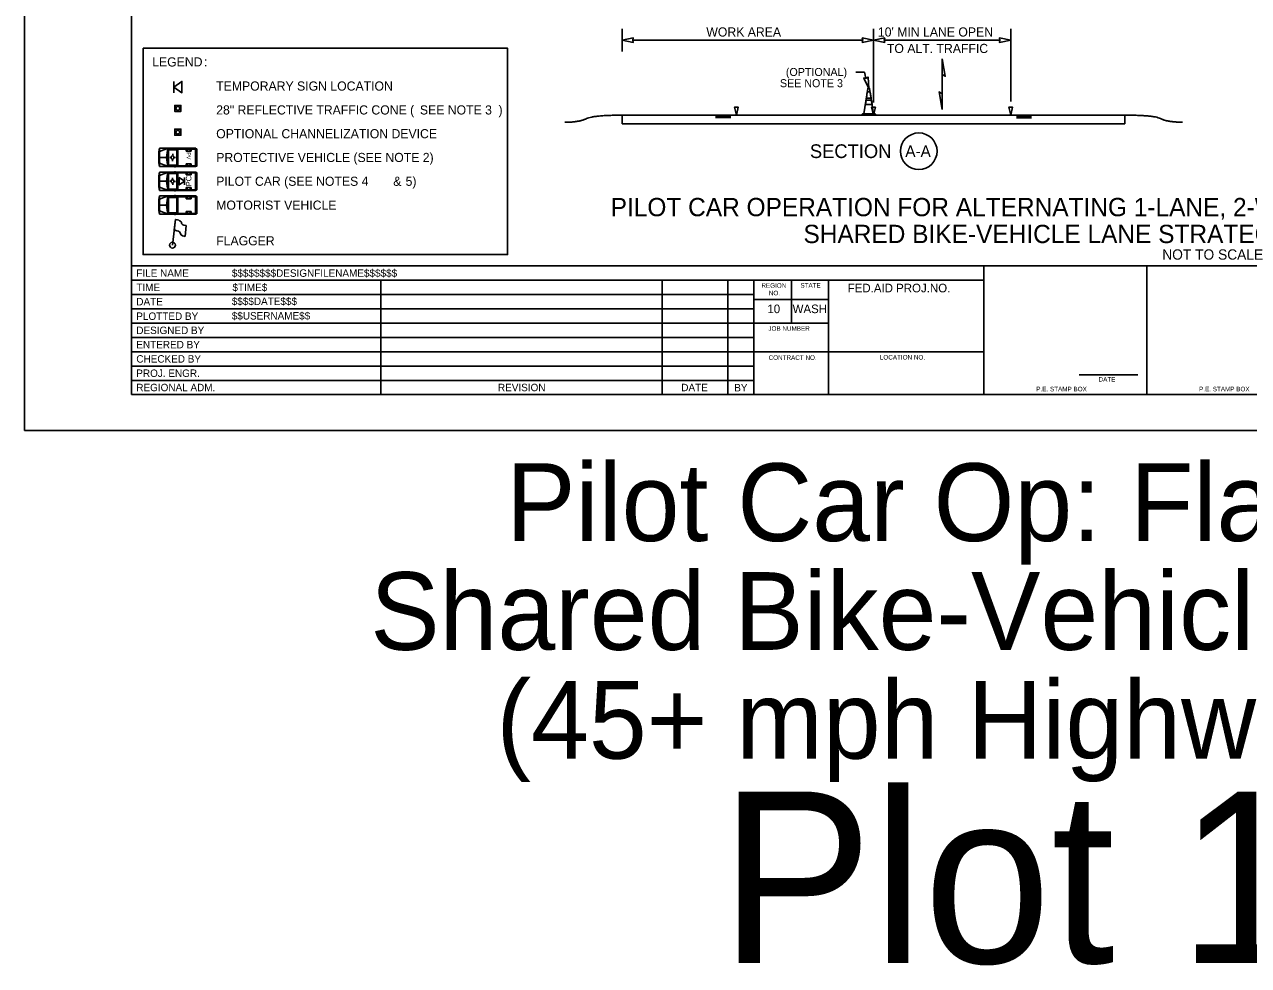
# Model space of a CAD drawing. Extents: x 99999.1 to 100095.7, y 99995 to 100010.7.
# Drawn here: x 99999.06 to 100009.77, y 99995.01 to 100003.24 of the extents above; entities that cross this region are included whole.
import ezdxf

# ---------------------------------------------------------------- set-up
doc = ezdxf.new("R2010")
doc.units = 0
for name, color, linetype in [('SH_DE_DetailHeading1Text', 7, 'Continuous'), ('SH_GI_PlotLimits', 7, 'Continuous'), ('SH_GI_SheetBorder', 7, 'Continuous'), ('SH_GI_SheetLocationText', 7, 'Continuous'), ('SH_GI_SheetTextInCells', 7, 'Continuous'), ('SH_GI_TitleBlockText', 7, 'Continuous'), ('TR_WZ_FlaggingStation', 7, 'Continuous'), ('TR_WZ_MotoristVehicle', 7, 'Continuous'), ('TR_WZ_PortableSignMountBlk-Org', 7, 'Continuous'), ('TR_WZ_PortableSignMountBlk-Wht', 7, 'Continuous'), ('TR_WZ_ProtectiveVehicle', 7, 'Continuous'), ('TR_WZ_TrafficCone', 7, 'Continuous'), ('TR_WZ_TrafficConeElev', 7, 'Continuous'), ('TR_WZ_WorkZoneDetails', 7, 'Continuous'), ('TR_WZ_WorkZoneTextCurrent', 7, 'Continuous')]:
    doc.layers.add(name, color=color, linetype=linetype)

msp = doc.modelspace()

# ---------------------------------------------------------------- linework, layer by layer
at = {"layer": 'SH_GI_PlotLimits'}
msp.add_lwpolyline([(99999.062, 99999.687), (100016.062, 99999.687), (100016.062, 100010.687), (99999.062, 100010.687)], close=True, dxfattribs=at)
at = {"layer": 'SH_GI_SheetBorder'}
for p, q in [((100000, 100010.375), (100000, 100000)), ((100000, 100001.126), (100015.75, 100001.126)), ((100007.457, 100000), (100007.457, 100001.126)), ((100008.883, 100000), (100008.883, 100001.126)), ((100000, 100001.001), (100007.457, 100001.001)), ((100002.179, 100001.001), (100002.179, 100000)), ((100004.641, 100001.001), (100004.641, 100000)), ((100005.216, 100001.001), (100005.216, 100000)), ((100005.445, 100001.001), (100005.445, 100000)), ((100005.772, 100000.625), (100005.772, 100001.001)), ((100006.096, 100000), (100006.096, 100001.001)), ((100000, 100000.876), (100002.182, 100000.876)), ((100002.182, 100000.876), (100005.447, 100000.876)), ((100006.096, 100000.831), (100005.447, 100000.831)), ((100000, 100000.751), (100002.182, 100000.751)), ((100002.182, 100000.751), (100005.447, 100000.751)), ((100000, 100000.625), (100005.447, 100000.625)), ((100006.096, 100000.625), (100005.447, 100000.625)), ((100000, 100000.5), (100005.447, 100000.5)), ((100000, 100000.375), (100005.447, 100000.375)), ((100007.457, 100000.375), (100005.447, 100000.375)), ((100000, 100000.25), (100005.447, 100000.25)), ((100000, 100000.125), (100005.447, 100000.125)), ((100008.29, 100000.173), (100008.802, 100000.173)), ((100000, 100000), (100015.75, 100000))]:
    msp.add_line(p, q, dxfattribs=at)
at = {"layer": 'TR_WZ_FlaggingStation'}
for p, q in [((100000.357, 100001.308), (100000.383, 100001.533)), ((100000.372, 100001.441), (100000.383, 100001.533)), ((100000.477, 100001.479), (100000.467, 100001.385)), ((100000.372, 100001.441), (100000.372, 100001.441))]:
    msp.add_line(p, q, dxfattribs=at)
for points in [[(100000.383, 100001.533), (100000.387, 100001.532), (100000.402, 100001.529), (100000.413, 100001.526), (100000.42, 100001.521), (100000.427, 100001.517), (100000.432, 100001.512), (100000.435, 100001.505), (100000.436, 100001.5), (100000.44, 100001.493), (100000.449, 100001.487), (100000.458, 100001.483), (100000.477, 100001.479)], [(100000.467, 100001.385), (100000.46, 100001.386), (100000.446, 100001.39), (100000.433, 100001.398), (100000.428, 100001.407), (100000.425, 100001.415), (100000.418, 100001.424), (100000.409, 100001.429), (100000.395, 100001.434), (100000.372, 100001.441)]]:
    msp.add_lwpolyline(points, dxfattribs=at)
msp.add_circle((100000.357, 100001.308), 0.026, dxfattribs=at)
at = {"layer": 'TR_WZ_MotoristVehicle'}
for p, q in [((100000.245, 100001.947), (100000.238, 100001.914)), ((100000.238, 100001.914), (100000.238, 100001.819)), ((100000.245, 100001.947), (100000.245, 100001.787)), ((100000.245, 100001.947), (100000.396, 100001.947)), ((100000.245, 100001.917), (100000.321, 100001.947)), ((100000.321, 100001.947), (100000.321, 100001.787)), ((100000.322, 100001.947), (100000.322, 100001.787)), ((100000.322, 100001.947), (100000.332, 100001.934)), ((100000.322, 100001.934), (100000.396, 100001.934)), ((100000.358, 100001.898), (100000.358, 100001.885)), ((100000.376, 100001.949), (100000.385, 100001.949)), ((100000.396, 100001.947), (100000.396, 100001.787)), ((100000.563, 100001.947), (100000.398, 100001.947)), ((100000.398, 100001.947), (100000.398, 100001.787)), ((100000.558, 100001.94), (100000.403, 100001.94)), ((100000.403, 100001.94), (100000.403, 100001.793)), ((100000.477, 100001.94), (100000.477, 100001.922)), ((100000.521, 100001.922), (100000.477, 100001.922)), ((100000.485, 100001.94), (100000.485, 100001.922)), ((100000.512, 100001.94), (100000.512, 100001.922)), ((100000.521, 100001.94), (100000.521, 100001.922)), ((100000.558, 100001.94), (100000.558, 100001.793)), ((100000.563, 100001.947), (100000.563, 100001.787)), ((100000.567, 100001.944), (100000.563, 100001.944)), ((100000.563, 100001.944), (100000.563, 100001.789)), ((100000.571, 100001.939), (100000.571, 100001.794)), ((100000.245, 100001.787), (100000.238, 100001.819)), ((100000.245, 100001.867), (100000.306, 100001.867)), ((100000.245, 100001.816), (100000.321, 100001.787)), ((100000.245, 100001.787), (100000.396, 100001.787)), ((100000.322, 100001.799), (100000.396, 100001.799)), ((100000.33, 100001.799), (100000.322, 100001.787)), ((100000.334, 100001.867), (100000.344, 100001.867)), ((100000.359, 100001.836), (100000.359, 100001.848)), ((100000.37, 100001.866), (100000.37, 100001.866)), ((100000.383, 100001.866), (100000.371, 100001.866)), ((100000.376, 100001.784), (100000.385, 100001.784)), ((100000.563, 100001.787), (100000.398, 100001.787)), ((100000.558, 100001.793), (100000.403, 100001.793)), ((100000.477, 100001.793), (100000.477, 100001.811)), ((100000.521, 100001.811), (100000.477, 100001.811)), ((100000.485, 100001.793), (100000.485, 100001.811)), ((100000.512, 100001.793), (100000.512, 100001.811)), ((100000.521, 100001.793), (100000.521, 100001.811)), ((100000.571, 100001.878), (100000.563, 100001.875)), ((100000.571, 100001.855), (100000.563, 100001.858)), ((100000.567, 100001.789), (100000.563, 100001.789)), ((100000.569, 100001.867), (100000.565, 100001.867)), ((100000.567, 100001.869), (100000.567, 100001.864)), ((100000.245, 100001.738), (100000.238, 100001.706)), ((100000.238, 100001.706), (100000.238, 100001.611)), ((100000.245, 100001.738), (100000.245, 100001.578)), ((100000.245, 100001.738), (100000.396, 100001.738)), ((100000.245, 100001.709), (100000.321, 100001.738)), ((100000.321, 100001.738), (100000.321, 100001.578)), ((100000.322, 100001.738), (100000.322, 100001.578)), ((100000.322, 100001.738), (100000.332, 100001.726)), ((100000.322, 100001.726), (100000.396, 100001.726)), ((100000.376, 100001.741), (100000.385, 100001.741)), ((100000.396, 100001.738), (100000.396, 100001.578)), ((100000.563, 100001.738), (100000.398, 100001.738)), ((100000.398, 100001.738), (100000.398, 100001.578)), ((100000.558, 100001.732), (100000.403, 100001.732)), ((100000.403, 100001.732), (100000.403, 100001.585)), ((100000.477, 100001.732), (100000.477, 100001.714)), ((100000.521, 100001.714), (100000.477, 100001.714)), ((100000.485, 100001.732), (100000.485, 100001.714)), ((100000.512, 100001.732), (100000.512, 100001.714)), ((100000.521, 100001.732), (100000.521, 100001.714)), ((100000.558, 100001.732), (100000.558, 100001.585)), ((100000.563, 100001.738), (100000.563, 100001.578)), ((100000.567, 100001.736), (100000.563, 100001.736)), ((100000.563, 100001.736), (100000.563, 100001.581)), ((100000.571, 100001.731), (100000.571, 100001.586)), ((100000.245, 100001.578), (100000.238, 100001.611)), ((100000.245, 100001.658), (100000.306, 100001.658)), ((100000.245, 100001.608), (100000.321, 100001.578)), ((100000.245, 100001.578), (100000.396, 100001.578)), ((100000.322, 100001.591), (100000.396, 100001.591)), ((100000.33, 100001.591), (100000.322, 100001.578)), ((100000.376, 100001.576), (100000.385, 100001.576)), ((100000.563, 100001.578), (100000.398, 100001.578)), ((100000.558, 100001.585), (100000.403, 100001.585)), ((100000.477, 100001.585), (100000.477, 100001.603)), ((100000.521, 100001.603), (100000.477, 100001.603)), ((100000.485, 100001.585), (100000.485, 100001.603)), ((100000.512, 100001.585), (100000.512, 100001.603)), ((100000.521, 100001.585), (100000.521, 100001.603)), ((100000.571, 100001.67), (100000.563, 100001.667)), ((100000.571, 100001.647), (100000.563, 100001.65)), ((100000.567, 100001.581), (100000.563, 100001.581)), ((100000.569, 100001.658), (100000.565, 100001.658)), ((100000.567, 100001.661), (100000.567, 100001.656))]:
    msp.add_line(p, q, dxfattribs=at)
for centre, major_axis, start_param, end_param in [((100000.429, 100001.867), (0, -0.168), 4.215667, 5.208926), ((100000.567, 100001.939), (0, 0.00488), 4.712389, 6.283185), ((100000.567, 100001.794), (0, -0.00488), 0, 1.570796), ((100000.429, 100001.658), (0, -0.168), 4.215667, 5.208926), ((100000.567, 100001.731), (0, 0.00488), 4.712389, 6.283185), ((100000.567, 100001.586), (0, -0.00488), 0, 1.570796)]:
    msp.add_ellipse(centre, major_axis=major_axis, ratio=0.73155, start_param=start_param, end_param=end_param, dxfattribs=at)
for centre, major_axis in [((100000.358, 100001.867), (0, 0.0154)), ((100000.567, 100001.867), (0, 0.00225)), ((100000.567, 100001.658), (0, 0.00225))]:
    msp.add_ellipse(centre, major_axis=major_axis, ratio=0.73155, dxfattribs=at)
at = {"layer": 'TR_WZ_PortableSignMountBlk-Org'}
msp.add_line((100000.368, 100002.641), (100000.368, 100002.741), dxfattribs=at)
msp.add_lwpolyline([(100000.368, 100002.691), (100000.44, 100002.741), (100000.44, 100002.641)], close=True, dxfattribs=at)
at = {"layer": 'TR_WZ_PortableSignMountBlk-Wht'}
msp.add_line((100000.462, 100001.899), (100000.462, 100001.835), dxfattribs=at)
msp.add_lwpolyline([(100000.462, 100001.867), (100000.416, 100001.835), (100000.416, 100001.899)], close=True, dxfattribs=at)
at = {"layer": 'TR_WZ_ProtectiveVehicle'}
for p, q in [((100000.245, 100002.155), (100000.238, 100002.123)), ((100000.238, 100002.027), (100000.238, 100002.123)), ((100000.245, 100001.995), (100000.245, 100002.155)), ((100000.245, 100002.155), (100000.396, 100002.155)), ((100000.245, 100002.126), (100000.321, 100002.155)), ((100000.321, 100001.995), (100000.321, 100002.155)), ((100000.322, 100001.995), (100000.322, 100002.155)), ((100000.33, 100002.142), (100000.322, 100002.155)), ((100000.322, 100002.142), (100000.396, 100002.142)), ((100000.359, 100002.106), (100000.359, 100002.094)), ((100000.376, 100002.157), (100000.385, 100002.157)), ((100000.396, 100001.995), (100000.396, 100002.155)), ((100000.563, 100002.155), (100000.398, 100002.155)), ((100000.398, 100001.995), (100000.398, 100002.155)), ((100000.558, 100002.148), (100000.403, 100002.148)), ((100000.403, 100002.001), (100000.403, 100002.148)), ((100000.477, 100002.148), (100000.477, 100002.13)), ((100000.521, 100002.13), (100000.477, 100002.13)), ((100000.485, 100002.148), (100000.485, 100002.13)), ((100000.512, 100002.148), (100000.512, 100002.13)), ((100000.521, 100002.148), (100000.521, 100002.13)), ((100000.558, 100002.001), (100000.558, 100002.148)), ((100000.563, 100001.995), (100000.563, 100002.155)), ((100000.567, 100002.152), (100000.563, 100002.152)), ((100000.563, 100001.998), (100000.563, 100002.152)), ((100000.571, 100002.002), (100000.571, 100002.147)), ((100000.245, 100001.995), (100000.238, 100002.027)), ((100000.245, 100002.075), (100000.306, 100002.075)), ((100000.245, 100002.024), (100000.321, 100001.995)), ((100000.245, 100001.995), (100000.396, 100001.995)), ((100000.322, 100001.995), (100000.332, 100002.007)), ((100000.322, 100002.007), (100000.396, 100002.007)), ((100000.334, 100002.075), (100000.344, 100002.075)), ((100000.358, 100002.043), (100000.358, 100002.056)), ((100000.37, 100002.075), (100000.37, 100002.075)), ((100000.383, 100002.075), (100000.371, 100002.075)), ((100000.563, 100001.995), (100000.398, 100001.995)), ((100000.558, 100002.001), (100000.403, 100002.001)), ((100000.521, 100002.02), (100000.477, 100002.02)), ((100000.477, 100002.001), (100000.477, 100002.02)), ((100000.485, 100002.001), (100000.485, 100002.02)), ((100000.512, 100002.001), (100000.512, 100002.02)), ((100000.521, 100002.001), (100000.521, 100002.02)), ((100000.571, 100002.086), (100000.563, 100002.083)), ((100000.571, 100002.064), (100000.563, 100002.067)), ((100000.567, 100001.998), (100000.563, 100001.998)), ((100000.569, 100002.075), (100000.565, 100002.075)), ((100000.567, 100002.073), (100000.567, 100002.077)), ((100000.376, 100001.993), (100000.385, 100001.993))]:
    msp.add_line(p, q, dxfattribs=at)
for centre, major_axis, start_param, end_param in [((100000.429, 100002.075), (0, -0.168), 4.215852, 5.209111), ((100000.567, 100002.147), (0, 0.00488), 4.712389, 6.283185), ((100000.567, 100002.002), (0, -0.00488), 6.283185, 7.853982)]:
    msp.add_ellipse(centre, major_axis=major_axis, ratio=0.73155, start_param=start_param, end_param=end_param, dxfattribs=at)
for centre, major_axis in [((100000.358, 100002.075), (0, 0.0154)), ((100000.567, 100002.075), (0, 0.00225))]:
    msp.add_ellipse(centre, major_axis=major_axis, ratio=0.73155, dxfattribs=at)
at = {"layer": 'TR_WZ_TrafficCone'}
for points in [[(100000.377, 100002.531), (100000.431, 100002.531), (100000.431, 100002.478), (100000.377, 100002.478), (100000.377, 100002.531)], [(100000.377, 100002.478), (100000.431, 100002.478), (100000.431, 100002.531), (100000.377, 100002.531), (100000.377, 100002.478)], [(100000.377, 100002.323), (100000.431, 100002.323), (100000.431, 100002.27), (100000.377, 100002.27), (100000.377, 100002.323)], [(100000.377, 100002.27), (100000.431, 100002.27), (100000.431, 100002.323), (100000.377, 100002.323), (100000.377, 100002.27)]]:
    msp.add_lwpolyline(points, dxfattribs=at)
for centre in [(100000.404, 100002.505), (100000.404, 100002.296)]:
    msp.add_circle(centre, 0.0167, dxfattribs=at)
at = {"layer": 'TR_WZ_TrafficConeElev'}
for p, q in [((100006.436, 100002.648), (100006.428, 100002.593)), ((100006.462, 100002.648), (100006.436, 100002.648)), ((100006.47, 100002.593), (100006.462, 100002.648)), ((100006.426, 100002.577), (100006.42, 100002.539)), ((100006.42, 100002.539), (100006.478, 100002.539)), ((100006.472, 100002.577), (100006.426, 100002.577)), ((100006.428, 100002.593), (100006.47, 100002.593)), ((100006.478, 100002.539), (100006.472, 100002.577)), ((100006.395, 100002.458), (100006.391, 100002.454)), ((100006.391, 100002.454), (100006.391, 100002.446)), ((100006.391, 100002.446), (100006.507, 100002.446)), ((100006.407, 100002.458), (100006.395, 100002.458)), ((100006.507, 100002.454), (100006.503, 100002.458)), ((100006.507, 100002.446), (100006.507, 100002.454))]:
    msp.add_line(p, q, dxfattribs=at)
msp.add_lwpolyline([(100006.407, 100002.458), (100006.491, 100002.458), (100006.457, 100002.679), (100006.441, 100002.679)], close=True, dxfattribs=at)
msp.add_lwpolyline([(100006.407, 100002.458), (100006.491, 100002.458), (100006.457, 100002.679), (100006.441, 100002.679)], close=True, dxfattribs=at)
msp.add_lwpolyline([(100006.503, 100002.458), (100006.491, 100002.458), (100006.407, 100002.458)], dxfattribs=at)
at = {"layer": 'TR_WZ_WorkZoneDetails'}
for p, q in [((100004.291, 100003.001), (100004.291, 100003.201)), ((100006.491, 100002.555), (100006.491, 100003.201)), ((100007.691, 100002.565), (100007.691, 100003.201)), ((100006.397, 100003.101), (100004.384, 100003.101)), ((100007.597, 100003.101), (100006.584, 100003.101)), ((100006.336, 100002.822), (100006.412, 100002.822)), ((100006.425, 100002.77), (100006.412, 100002.822)), ((100007.091, 100002.802), (100007.091, 100002.633)), ((100007.091, 100002.633), (100007.091, 100002.802)), ((100004.291, 100002.445), (100004.291, 100002.37)), ((100008.691, 100002.445), (100004.291, 100002.445)), ((100005.108, 100002.44), (100005.241, 100002.44)), ((100005.108, 100002.435), (100005.241, 100002.435)), ((100005.108, 100002.429), (100005.241, 100002.429)), ((100005.108, 100002.424), (100005.241, 100002.424)), ((100007.874, 100002.44), (100007.741, 100002.44)), ((100007.874, 100002.434), (100007.741, 100002.434)), ((100007.874, 100002.428), (100007.741, 100002.428)), ((100007.874, 100002.423), (100007.741, 100002.423)), ((100008.691, 100002.445), (100008.691, 100002.37)), ((100008.691, 100002.37), (100004.291, 100002.37))]:
    msp.add_line(p, q, dxfattribs=at)
for points in [[(100004.291, 100003.101), (100004.389, 100003.082), (100004.384, 100003.101), (100004.389, 100003.121)], [(100006.491, 100003.101), (100006.392, 100003.082), (100006.397, 100003.101), (100006.392, 100003.121)], [(100006.491, 100003.101), (100006.589, 100003.082), (100006.584, 100003.101), (100006.589, 100003.121)], [(100007.691, 100003.101), (100007.592, 100003.082), (100007.597, 100003.101), (100007.592, 100003.121)], [(100007.091, 100002.939), (100007.118, 100002.786), (100007.091, 100002.802)], [(100006.449, 100002.679), (100006.406, 100002.769), (100006.426, 100002.77), (100006.443, 100002.779)], [(100007.091, 100002.495), (100007.064, 100002.649), (100007.091, 100002.633)], [(100005.291, 100002.445), (100005.274, 100002.515), (100005.307, 100002.515)], [(100006.491, 100002.445), (100006.474, 100002.515), (100006.507, 100002.515)], [(100007.691, 100002.445), (100007.674, 100002.515), (100007.707, 100002.515)]]:
    msp.add_lwpolyline(points, close=True, dxfattribs=at)
for points in [[(100005.307, 100002.515), (100005.274, 100002.515), (100005.291, 100002.445), (100005.307, 100002.515)], [(100006.507, 100002.515), (100006.474, 100002.515), (100006.491, 100002.445), (100006.507, 100002.515)], [(100007.707, 100002.515), (100007.674, 100002.515), (100007.691, 100002.445), (100007.707, 100002.515)]]:
    msp.add_lwpolyline(points, dxfattribs=at)
msp.add_circle((100006.887, 100002.13), 0.16, dxfattribs=at)
for points in [[(100004.291, 100002.445), (100004.04, 100002.445), (100003.914, 100002.383), (100003.789, 100002.383)], [(100008.691, 100002.445), (100008.942, 100002.446), (100009.067, 100002.383), (100009.193, 100002.384)]]:
    msp.add_open_spline(points, degree=2, dxfattribs=at)
at = {"layer": 'TR_WZ_WorkZoneTextCurrent'}
msp.add_lwpolyline([(100000.1, 100003.031), (100003.289, 100003.031), (100003.289, 100001.226), (100000.1, 100001.226)], close=True, dxfattribs=at)

# ---------------------------------------------------------------- texts
at = {"layer": 'SH_DE_DetailHeading1Text'}
for s, height, p in [('PILOT CAR OPERATION FOR ALTERNATING 1-LANE, 2-WAY TRAFFIC: FLAGGER-CONTROLLED', 0.16, (100004.191, 100001.561)), ('SHARED BIKE-VEHICLE LANE STRATEGY (45+ MPH HIGHWAYS)', 0.16, (100005.878, 100001.326)), ('NOT TO SCALE', 0.09, (100009.017, 100001.181))]:
    msp.add_text(s, height=height, rotation=360, dxfattribs=at).set_placement(p)
at = {"layer": 'SH_GI_SheetLocationText'}
for s, height, p in [('Pilot Car Op: Flagger', 0.68, (100003.277, 99998.719)), ('Shared Bike-Vehicle Lane', 0.68, (100002.088, 99997.767)), ('(45+ mph Highways)', 0.68, (100003.192, 99996.815)), ('Plot 1', 1.5, (100005.145, 99995.027))]:
    msp.add_text(s, height=height, dxfattribs=at).set_placement(p)
at = {"layer": 'SH_GI_SheetTextInCells'}
for s, height, p in [('FILE NAME', 0.0651, (100000.041, 100001.031)), ('TIME', 0.0651, (100000.041, 100000.906)), ('REGION', 0.04, (100005.51, 100000.935)), ('STATE', 0.04, (100005.851, 100000.936)), ('FED.AID PROJ.NO.', 0.07506, (100006.265, 100000.895)), ('DATE', 0.0651, (100000.041, 100000.781)), ('NO.', 0.04, (100005.575, 100000.869)), ('PLOTTED BY', 0.0651, (100000.041, 100000.654)), ('10', 0.0751, (100005.562, 100000.713)), ('WASH', 0.0751, (100005.783, 100000.713)), ('DESIGNED BY', 0.06505, (100000.041, 100000.53)), ('JOB NUMBER', 0.04, (100005.571, 100000.559)), ('ENTERED BY', 0.0651, (100000.041, 100000.405)), ('CHECKED BY', 0.0651, (100000.041, 100000.28)), ('CONTRACT NO.', 0.04003, (100005.573, 100000.304)), ('LOCATION NO.', 0.04003, (100006.546, 100000.307)), ('PROJ. ENGR.', 0.06505, (100000.041, 100000.155)), ('REGIONAL ADM.', 0.06505, (100000.041, 100000.03)), ('REVISION', 0.0651, (100003.205, 100000.03)), ('DATE', 0.0651, (100004.809, 100000.03)), ('BY', 0.0651, (100005.272, 100000.028)), ('P.E. STAMP BOX', 0.04003, (100007.915, 100000.029)), ('DATE', 0.04, (100008.46, 100000.114)), ('P.E. STAMP BOX', 0.04003, (100009.339, 100000.029))]:
    msp.add_text(s, height=height, dxfattribs=at).set_placement(p)
at = {"layer": 'SH_GI_TitleBlockText'}
for s, height, p in [('$$$$$$$$DESIGNFILENAME$$$$$$', 0.06505, (100000.877, 100001.031)), ('$TIME$', 0.0651, (100000.882, 100000.906)), ('$$$$DATE$$$', 0.06505, (100000.876, 100000.784)), ('$$USERNAME$$', 0.06505, (100000.876, 100000.657))]:
    msp.add_text(s, height=height, dxfattribs=at).set_placement(p)
at = {"layer": 'TR_WZ_MotoristVehicle'}
msp.add_text('PC', height=0.048, rotation=90, dxfattribs=at).set_placement((100000.523, 100001.822))
at = {"layer": 'TR_WZ_ProtectiveVehicle'}
msp.add_text('PV', height=0.0334, rotation=270, dxfattribs=at).set_placement((100000.482, 100002.12))
at = {"layer": 'TR_WZ_WorkZoneDetails'}
for s, p in [('WORK AREA', (100005.028, 100003.133)), ("10' MIN LANE OPEN", (100006.529, 100003.133)), ('TO ALT. TRAFFIC', (100006.608, 100002.989))]:
    msp.add_text(s, height=0.08, dxfattribs=at).set_placement(p)
for s, height, p in [('SECTION', 0.12, (100005.934, 100002.07)), ('A-A', 0.1, (100006.769, 100002.08))]:
    msp.add_text(s, height=height, rotation=360, dxfattribs=at).set_placement(p)
at = {"layer": 'TR_WZ_WorkZoneTextCurrent'}
for s, p in [('LEGEND', (100000.18, 100002.871)), (':', (100000.633, 100002.871)), ('TEMPORARY SIGN LOCATION ', (100000.74, 100002.66)), ('28" REFLECTIVE TRAFFIC CONE (', (100000.74, 100002.451)), ('SEE NOTE 3', (100002.522, 100002.451)), (')', (100003.21, 100002.451)), ('OPTIONAL CHANNELIZATION DEVICE', (100000.74, 100002.243)), ('PROTECTIVE VEHICLE (SEE NOTE 2)', (100000.74, 100002.035)), ('PILOT CAR (SEE NOTES 4', (100000.74, 100001.827)), ('&', (100002.289, 100001.827)), ('5)', (100002.397, 100001.827)), ('MOTORIST VEHICLE', (100000.74, 100001.618)), ('FLAGGER', (100000.74, 100001.306))]:
    msp.add_text(s, height=0.08, rotation=360, dxfattribs=at).set_placement(p)
for s, p in [('(OPTIONAL)', (100005.724, 100002.788)), ('SEE NOTE 3', (100005.672, 100002.69))]:
    msp.add_text(s, height=0.07, dxfattribs=at).set_placement(p)

doc.saveas('drawing.dxf')
